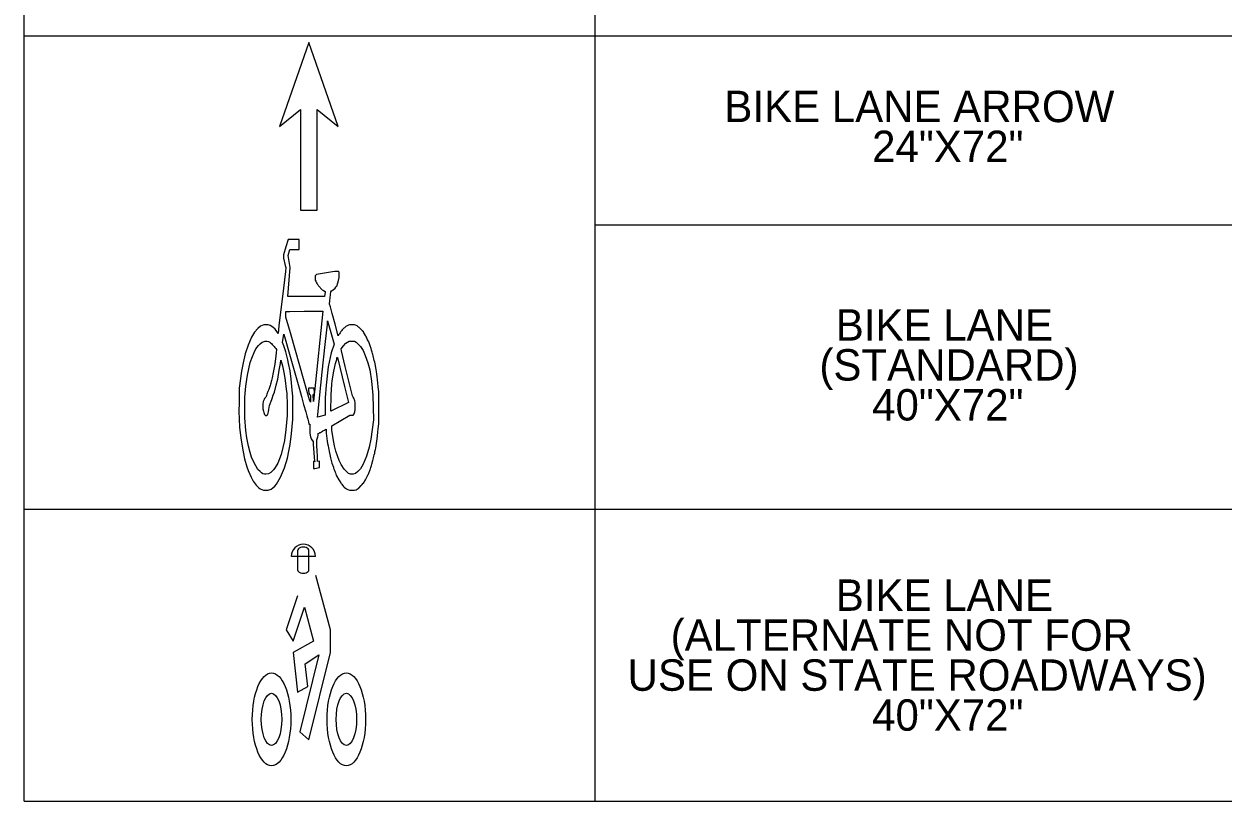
# Model space of a CAD drawing. Extents: x 9999.9 to 10007, y 10023.6 to 10033.8.
# Drawn here: x 9999.907 to 10002.196, y 10025.094 to 10026.578 of the extents above; entities that cross this region are included whole.
import ezdxf

# ---------------------------------------------------------------- set-up
doc = ezdxf.new("R2010")
doc.units = 0
doc.layers.add('DETL-LINE', color=7, linetype='Continuous')
doc.layers.add('DETL-NOTE', color=7, linetype='Continuous')

msp = doc.modelspace()

# ---------------------------------------------------------------- linework, layer by layer
at = {"layer": 'DETL-LINE'}
msp.add_line((10000.449, 10025.561), (10000.4175, 10025.561), dxfattribs=at)
msp.add_lwpolyline([(10000.4351, 10026.2225), (10000.4671, 10026.2225), (10000.4671, 10026.4145), (10000.5071, 10026.3825), (10000.4511, 10026.5425), (10000.3951, 10026.3825), (10000.4351, 10026.4145)], close=True, dxfattribs=at)
for points in [[(10000.4808, 10026.0572), (10000.4106, 10026.0572), (10000.4154, 10026.1128), (10000.4113, 10026.1357), (10000.4147, 10026.1476), (10000.4323, 10026.1476), (10000.4323, 10026.1665), (10000.4114, 10026.1664), (10000.4069, 10026.1523), (10000.4026, 10026.1368), (10000.4027, 10026.1309), (10000.4058, 10026.1166), (10000.4067, 10026.1132), (10000.4063, 10026.1052), (10000.4025, 10026.0735), (10000.3937, 10026.0014), (10000.3923, 10025.987), (10000.3896, 10025.9908), (10000.3865, 10025.9948), (10000.3822, 10025.9987), (10000.377, 10026.0018), (10000.3734, 10026.0032), (10000.3647, 10026.0031), (10000.3589, 10026.0008), (10000.3538, 10025.9967), (10000.3473, 10025.9894), (10000.3415, 10025.9796), (10000.335, 10025.9648), (10000.3296, 10025.9479), (10000.3257, 10025.931), (10000.3226, 10025.9149), (10000.3182, 10025.8824), (10000.3178, 10025.8543), (10000.3175, 10025.8386), (10000.3188, 10025.8082), (10000.321, 10025.7866), (10000.3255, 10025.7607), (10000.3282, 10025.7475), (10000.3327, 10025.7324), (10000.3352, 10025.7251), (10000.3409, 10025.7122), (10000.3449, 10025.7046), (10000.3506, 10025.6969), (10000.3549, 10025.6925), (10000.3583, 10025.6898), (10000.3641, 10025.6874), (10000.3735, 10025.6874), (10000.3789, 10025.6894), (10000.3822, 10025.6921), (10000.3863, 10025.6955), (10000.3891, 10025.6989), (10000.3971, 10025.7124), (10000.4046, 10025.7299), (10000.4099, 10025.7488), (10000.413, 10025.7618), (10000.4153, 10025.7749), (10000.4181, 10025.7959), (10000.4201, 10025.8223), (10000.4201, 10025.867), (10000.4192, 10025.8784), (10000.4172, 10025.8997), (10000.4151, 10025.9157), (10000.4123, 10025.9294), (10000.4109, 10025.9366), (10000.4067, 10025.952), (10000.4033, 10025.9631), (10000.4006, 10025.9697), (10000.403, 10025.9856), (10000.4151, 10025.9431), (10000.4329, 10025.8808), (10000.4366, 10025.8666), (10000.441, 10025.8514), (10000.4451, 10025.8373), (10000.4471, 10025.8298), (10000.4483, 10025.8251), (10000.4491, 10025.8232), (10000.4504, 10025.8183), (10000.4512, 10025.8136), (10000.4525, 10025.8136), (10000.4525, 10025.7967), (10000.4538, 10025.7893), (10000.4545, 10025.7873), (10000.4552, 10025.7859), (10000.4566, 10025.784), (10000.4578, 10025.7818), (10000.4592, 10025.7819), (10000.4592, 10025.7752), (10000.4612, 10025.7508), (10000.4618, 10025.7427), (10000.4627, 10025.7421), (10000.4618, 10025.7421), (10000.4598, 10025.7421), (10000.4598, 10025.7292), (10000.4625, 10025.7292), (10000.4713, 10025.7306), (10000.4714, 10025.7427), (10000.4673, 10025.7426), (10000.4673, 10025.7526), (10000.4667, 10025.7628), (10000.4659, 10025.7723), (10000.4659, 10025.7838), (10000.4666, 10025.7853), (10000.4673, 10025.7872), (10000.468, 10025.7893), (10000.4687, 10025.7919), (10000.4687, 10025.7959), (10000.4706, 10025.7967), (10000.4719, 10025.7974), (10000.4733, 10025.798), (10000.4767, 10025.8001), (10000.4775, 10025.8008), (10000.4794, 10025.8014), (10000.4807, 10025.8021), (10000.4828, 10025.8035), (10000.4842, 10025.8041), (10000.4842, 10025.7967), (10000.4855, 10025.786), (10000.4862, 10025.7812), (10000.4868, 10025.7765), (10000.4875, 10025.7724), (10000.4882, 10025.7682), (10000.4889, 10025.765), (10000.4896, 10025.7616), (10000.4909, 10025.7556), (10000.4923, 10025.7495), (10000.495, 10025.7393), (10000.4977, 10025.7312), (10000.4983, 10025.7293), (10000.499, 10025.7273), (10000.4997, 10025.7252), (10000.5004, 10025.7238), (10000.5011, 10025.7218), (10000.5017, 10025.7204), (10000.5024, 10025.7184), (10000.5031, 10025.7171), (10000.504, 10025.715), (10000.5079, 10025.7076), (10000.5092, 10025.7056), (10000.5106, 10025.7035), (10000.5119, 10025.7016), (10000.5125, 10025.7002), (10000.5139, 10025.6989), (10000.5153, 10025.6969), (10000.5173, 10025.6948), (10000.5186, 10025.6934), (10000.5206, 10025.6914), (10000.5226, 10025.6901), (10000.524, 10025.6894), (10000.5253, 10025.6886), (10000.5287, 10025.6874), (10000.5381, 10025.6873), (10000.5415, 10025.6884), (10000.5429, 10025.6894), (10000.5449, 10025.6907), (10000.5462, 10025.6913), (10000.551, 10025.6962), (10000.553, 10025.6982), (10000.5543, 10025.7002), (10000.555, 10025.7008), (10000.5564, 10025.7029), (10000.5574, 10025.7044), (10000.5591, 10025.7076), (10000.5604, 10025.7096), (10000.5611, 10025.711), (10000.5618, 10025.7124), (10000.5624, 10025.7137), (10000.563, 10025.7147), (10000.5638, 10025.717), (10000.5645, 10025.7184), (10000.5652, 10025.7197), (10000.5658, 10025.7218), (10000.5665, 10025.7231), (10000.5671, 10025.7252), (10000.5679, 10025.7272), (10000.5686, 10025.7286), (10000.5692, 10025.7306), (10000.5699, 10025.7326), (10000.5705, 10025.7346), (10000.5712, 10025.7373), (10000.5719, 10025.7393), (10000.5726, 10025.7421), (10000.5733, 10025.7441), (10000.5739, 10025.7468), (10000.5746, 10025.7495), (10000.5753, 10025.7522), (10000.5759, 10025.7549), (10000.5766, 10025.7583), (10000.5772, 10025.7616), (10000.578, 10025.765), (10000.5786, 10025.768), (10000.5794, 10025.7725), (10000.58, 10025.7765), (10000.5807, 10025.7813), (10000.5814, 10025.7859), (10000.582, 10025.7913), (10000.5827, 10025.7981), (10000.5834, 10025.8047), (10000.5847, 10025.8144), (10000.5847, 10025.8758), (10000.5833, 10025.8851), (10000.5827, 10025.8924), (10000.582, 10025.8986), (10000.5813, 10025.9046), (10000.5808, 10025.9092), (10000.58, 10025.914), (10000.5793, 10025.9181), (10000.5786, 10025.9214), (10000.578, 10025.9256), (10000.5773, 10025.9289), (10000.5766, 10025.9323), (10000.5759, 10025.9351), (10000.5753, 10025.9383), (10000.5745, 10025.9411), (10000.5739, 10025.9439), (10000.5732, 10025.9467), (10000.5725, 10025.9486), (10000.572, 10025.9512), (10000.5705, 10025.9552), (10000.5699, 10025.958), (10000.5692, 10025.9599), (10000.5685, 10025.9614), (10000.5678, 10025.9634), (10000.5672, 10025.9654), (10000.5665, 10025.9674), (10000.5658, 10025.9687), (10000.5652, 10025.9708), (10000.5624, 10025.9762), (10000.5618, 10025.9782), (10000.5611, 10025.9796), (10000.5598, 10025.9816), (10000.5591, 10025.983), (10000.5574, 10025.9863), (10000.5557, 10025.9884), (10000.555, 10025.9897), (10000.553, 10025.9918), (10000.5523, 10025.9931), (10000.5469, 10025.9985), (10000.5456, 10025.9992), (10000.5442, 10026.0005), (10000.5429, 10026.0012), (10000.5402, 10026.0025), (10000.5382, 10026.0032), (10000.5287, 10026.0032), (10000.5267, 10026.0025), (10000.524, 10026.0012), (10000.5213, 10025.9999), (10000.5193, 10025.9978), (10000.518, 10025.9972), (10000.5146, 10025.9938), (10000.5132, 10025.9917), (10000.5119, 10025.9904), (10000.5106, 10025.9884), (10000.5092, 10025.9864), (10000.5078, 10025.9843), (10000.5067, 10025.9826), (10000.5011, 10026.0044), (10000.4956, 10026.0248), (10000.4923, 10026.0376), (10000.4902, 10026.043), (10000.491, 10026.0498), (10000.4916, 10026.0551), (10000.4923, 10026.0613), (10000.493, 10026.0667), (10000.4943, 10026.0681), (10000.4963, 10026.0693), (10000.4976, 10026.07), (10000.501, 10026.0734), (10000.5024, 10026.0754), (10000.5029, 10026.0768), (10000.5041, 10026.0775), (10000.5063, 10026.0836), (10000.5077, 10026.0878), (10000.5091, 10026.0937), (10000.5091, 10026.1038), (10000.5078, 10026.1051), (10000.5005, 10026.1051), (10000.4958, 10026.1045), (10000.4654, 10026.0998), (10000.4641, 10026.0983), (10000.4633, 10026.0971), (10000.4632, 10026.0884), (10000.464, 10026.0869), (10000.4647, 10026.0849), (10000.4653, 10026.0838), (10000.4667, 10026.0816), (10000.4673, 10026.0802), (10000.4687, 10026.079), (10000.4694, 10026.0778), (10000.4765, 10026.0705), (10000.4777, 10026.0697), (10000.4789, 10026.0687), (10000.4821, 10026.0673), (10000.4822, 10026.066), (10000.4808, 10026.0572)], [(10000.4069, 10026.0237), (10000.4073, 10026.0288), (10000.4146, 10026.0288), (10000.4423, 10026.0294), (10000.4776, 10026.0293), (10000.4617, 10025.8757), (10000.4612, 10025.8703), (10000.4598, 10025.8572), (10000.4593, 10025.8705), (10000.4612, 10025.8703), (10000.4617, 10025.8757), (10000.4612, 10025.8811), (10000.4606, 10025.8824), (10000.4504, 10025.8825), (10000.4504, 10025.877), (10000.4513, 10025.871), (10000.4531, 10025.871), (10000.4538, 10025.8675), (10000.4538, 10025.8554), (10000.4524, 10025.8602), (10000.4421, 10025.8957), (10000.4157, 10025.9879), (10000.4068, 10026.0178), (10000.4069, 10026.0237)], [(10000.4677, 10025.8267), (10000.4679, 10025.8319), (10000.4765, 10025.913), (10000.4822, 10025.9661), (10000.4864, 10026.0045), (10000.4867, 10026.0109), (10000.4991, 10025.9666), (10000.4936, 10025.9502), (10000.488, 10025.9234), (10000.4837, 10025.8883), (10000.4823, 10025.8639), (10000.4823, 10025.831), (10000.4677, 10025.8267)], [(10000.3965, 10025.9297), (10000.3975, 10025.9357), (10000.4005, 10025.9248), (10000.404, 10025.9092), (10000.406, 10025.8972), (10000.4079, 10025.8802), (10000.4086, 10025.8722), (10000.4098, 10025.8503), (10000.4093, 10025.8303), (10000.4072, 10025.8035), (10000.4043, 10025.7826), (10000.3979, 10025.7555), (10000.3916, 10025.7392), (10000.3868, 10025.731), (10000.3836, 10025.7265), (10000.3786, 10025.7214), (10000.3738, 10025.7188), (10000.3691, 10025.7179), (10000.3664, 10025.7183), (10000.3629, 10025.719), (10000.3604, 10025.7208), (10000.3578, 10025.7234), (10000.3537, 10025.7271), (10000.3456, 10025.7413), (10000.3417, 10025.7509), (10000.3389, 10025.7594), (10000.3358, 10025.7714), (10000.3328, 10025.7874), (10000.3308, 10025.8014), (10000.329, 10025.8255), (10000.3288, 10025.8651), (10000.3305, 10025.8863), (10000.3337, 10025.9075), (10000.3392, 10025.9314), (10000.3432, 10025.9427), (10000.3465, 10025.9508), (10000.35, 10025.9574), (10000.3545, 10025.9639), (10000.3577, 10025.9673), (10000.362, 10025.9703), (10000.3674, 10025.9722), (10000.371, 10025.9723), (10000.3742, 10025.9714), (10000.3766, 10025.97), (10000.378, 10025.9689), (10000.3796, 10025.9676), (10000.3811, 10025.966), (10000.3831, 10025.9642), (10000.3848, 10025.9623), (10000.386, 10025.9604), (10000.3877, 10025.958), (10000.3889, 10025.9563), (10000.3888, 10025.9499), (10000.3877, 10025.9443), (10000.3857, 10025.9282), (10000.3829, 10025.9121), (10000.3809, 10025.9022), (10000.3796, 10025.8969), (10000.379, 10025.8951), (10000.3784, 10025.8922), (10000.3775, 10025.8903), (10000.377, 10025.8875), (10000.3762, 10025.8856), (10000.3755, 10025.8834), (10000.3743, 10025.8796), (10000.3729, 10025.8762), (10000.3707, 10025.8709), (10000.3701, 10025.8685), (10000.3694, 10025.8667), (10000.3688, 10025.8654), (10000.366, 10025.8625), (10000.3654, 10025.861), (10000.3648, 10025.8592), (10000.364, 10025.8567), (10000.3633, 10025.852), (10000.3633, 10025.8432), (10000.3641, 10025.8384), (10000.3648, 10025.8358), (10000.3654, 10025.8337), (10000.3661, 10025.8324), (10000.3671, 10025.8312), (10000.3682, 10025.8304), (10000.3708, 10025.8305), (10000.3717, 10025.8312), (10000.3727, 10025.8335), (10000.3734, 10025.8346), (10000.3742, 10025.8373), (10000.3748, 10025.8414), (10000.3756, 10025.849), (10000.3802, 10025.8609), (10000.3831, 10025.8689), (10000.3851, 10025.875), (10000.3887, 10025.8881), (10000.3914, 10025.8997), (10000.3944, 10025.9166), (10000.3965, 10025.9297)], [(10000.4949, 10025.802), (10000.4946, 10025.8103), (10000.5294, 10025.8307), (10000.5356, 10025.8306), (10000.5375, 10025.8331), (10000.5389, 10025.8374), (10000.5396, 10025.8416), (10000.5396, 10025.8543), (10000.5388, 10025.8582), (10000.5367, 10025.8636), (10000.5355, 10025.8649), (10000.534, 10025.8676), (10000.5203, 10025.924), (10000.513, 10025.9539), (10000.5124, 10025.9577), (10000.5173, 10025.9635), (10000.5218, 10025.9681), (10000.5249, 10025.9703), (10000.528, 10025.972), (10000.5297, 10025.9722), (10000.5328, 10025.9725), (10000.5358, 10025.9724), (10000.5383, 10025.9723), (10000.5414, 10025.9702), (10000.546, 10025.9659), (10000.5496, 10025.9617), (10000.5545, 10025.9541), (10000.5586, 10025.9449), (10000.5634, 10025.9306), (10000.5671, 10025.9173), (10000.5708, 10025.896), (10000.5733, 10025.8689), (10000.5741, 10025.8218), (10000.5692, 10025.785), (10000.5661, 10025.7695), (10000.5609, 10025.7523), (10000.5549, 10025.7372), (10000.5496, 10025.7286), (10000.5446, 10025.7233), (10000.5398, 10025.7194), (10000.5353, 10025.7182), (10000.5302, 10025.7183), (10000.5268, 10025.7195), (10000.5238, 10025.7217), (10000.5184, 10025.7274), (10000.5126, 10025.7363), (10000.5087, 10025.7444), (10000.5055, 10025.7531), (10000.5024, 10025.7623), (10000.5, 10025.7724), (10000.4972, 10025.786), (10000.4949, 10025.802)], [(10000.4931, 10025.8382), (10000.4938, 10025.8688), (10000.495, 10025.8899), (10000.4956, 10025.8966), (10000.4984, 10025.9148), (10000.5017, 10025.9295), (10000.5044, 10025.9372), (10000.5043, 10025.9412), (10000.5055, 10025.9412), (10000.5192, 10025.8854), (10000.5267, 10025.8553), (10000.4931, 10025.8382)], [(10000.4295, 10025.5721), (10000.4295, 10025.5353)], [(10000.4636, 10025.561), (10000.449, 10025.561)], [(10000.4511, 10025.5353), (10000.4511, 10025.5721)], [(10000.4295, 10025.4855), (10000.4078, 10025.4206), (10000.4208, 10025.399), (10000.4425, 10025.4639), (10000.46, 10025.399), (10000.4208, 10025.3773), (10000.4295, 10025.3016), (10000.4491, 10025.3124), (10000.4441, 10025.3557), (10000.4701, 10025.373), (10000.4338, 10025.2259), (10000.4511, 10025.2107), (10000.4922, 10025.3773), (10000.4922, 10025.4206), (10000.4641, 10025.5245)]]:
    msp.add_lwpolyline(points, dxfattribs=at)
msp.add_arc((10000.4405, 10025.561), 0.0231, 0, 180, dxfattribs=at)
for centre, start_param, end_param in [((10000.4403, 10025.5721), 3.141585, 6.283185), ((10000.4403, 10025.5353), 0, 3.1416)]:
    msp.add_ellipse(centre, major_axis=(-0.0108, 0), ratio=0.6, start_param=start_param, end_param=end_param, dxfattribs=at)
for centre, major_axis, ratio in [((10000.3797, 10025.2497), (0, -0.0887), 0.414634), ((10000.5225, 10025.2497), (0, -0.0887), 0.414634), ((10000.3797, 10025.2497), (0, -0.0498), 0.391304), ((10000.5225, 10025.2497), (0, -0.0498), 0.391304)]:
    msp.add_ellipse(centre, major_axis=major_axis, ratio=ratio, dxfattribs=at)
at = {"layer": 'DETL-NOTE'}
for p, q in [((9999.9071, 10025.0937), (9999.9071, 10033.8463)), ((10000.9969, 10033.4982), (10000.9969, 10025.0937)), ((9999.9071, 10026.5552), (10003.5339, 10026.5552)), ((10000.9969, 10026.1947), (10003.5339, 10026.1947)), ((9999.9071, 10025.6513), (10003.5339, 10025.6513)), ((9999.9071, 10025.0937), (10003.5339, 10025.0937))]:
    msp.add_line(p, q, dxfattribs=at)

# ---------------------------------------------------------------- texts
for s, p in [('BIKE LANE ARROW', (10001.2442, 10026.3906)), ('24"X72"', (10001.5263, 10026.3143)), ('BIKE LANE', (10001.4569, 10025.9732)), ('(STANDARD)', (10001.4257, 10025.8969)), ('40"X72"', (10001.5263, 10025.8206)), ('BIKE LANE', (10001.4569, 10025.457)), ('(ALTERNATE NOT FOR', (10001.1417, 10025.3807)), ('USE ON STATE ROADWAYS)', (10001.0594, 10025.3043)), ('40"X72"', (10001.5263, 10025.228))]:
    msp.add_text(s, height=0.06, dxfattribs=at).set_placement(p)

doc.saveas('drawing.dxf')
